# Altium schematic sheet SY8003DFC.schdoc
size 127 x 101 mm
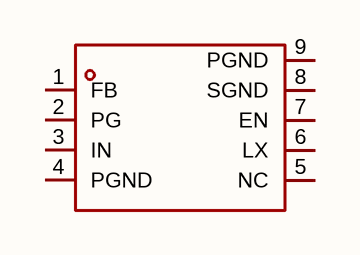
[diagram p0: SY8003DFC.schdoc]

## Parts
U?  sy8003dfc  [DFN-8_L2.0-W2.0-P0.50-BL-EP]  (value not drawn)

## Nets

Not connected (* = marked no-connect by the designer): U? 1(FB) 2(PG) 3(IN) 4(PGND) 5(NC) 6(LX) 7(EN) 8(SGND) 9(PGND)

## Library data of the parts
U? = sy8003dfc: 功能类型:降压型;工作电压:2.7V~5.5V;输出电压:-;输出电流:3A;输出类型:可调;; Manufacturer: Silergy(矽力杰); AddInBom: yes; ModelId: ea9fe5daec6c437ca860910abaae89ca; ModelName: DFN-8_L2.0-W2.0-H0.8-P0.50; ModelTransform: 78.74,77.961,0,90,0,0,0,0,0; Function: 降压型; Output Current: 3A; Frequency - Switching: 800kHz~1.2MHz; Synchronous Rectifier: 是; Number of Outputs: 1; Topology: 降压式; Quiescent Current: 55uA; Switch tube (built-in/external): 内置; Output Type: 可调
